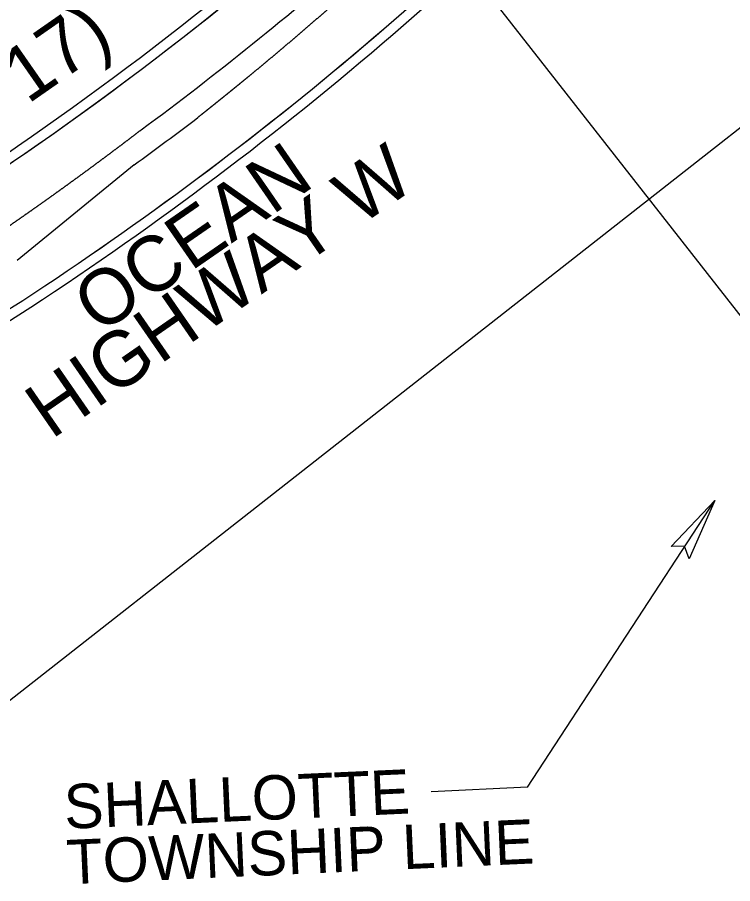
# Model space of a CAD drawing. Extents: x 2170913 to 2188101, y 74009 to 87693.
# Drawn here: x 2175946 to 2176656, y 76181 to 77040 of the extents above; entities that cross this region are included whole.
import ezdxf

# ---------------------------------------------------------------- set-up
doc = ezdxf.new("R2010")
doc.units = 0
for name, color, linetype in [('CTL Primary Horizontal and Vertical Cogo Elevation', 7, 'Continuous'), ('Exist Property Iron Pin CELL', 7, 'Continuous'), ('Exist Property Iron Pin Cogo Number', 7, 'Continuous'), ('Exist Right of Way Monument CELL', 7, 'Continuous'), ('Exist Utilities Water Fire Hydrant CELL', 7, 'Continuous')]:
    doc.layers.add(name, color=color, linetype=linetype)

msp = doc.modelspace()

# ---------------------------------------------------------------- linework, layer by layer
at = {"layer": 'CTL Primary Horizontal and Vertical Cogo Elevation'}
for q in [(2176638.43, 76560.83), (2176356.96, 76271.7)]:
    msp.add_line((2176452.51, 76276.24), q, dxfattribs=at)
at = {"layer": 'Exist Property Iron Pin Cogo Number'}
msp.add_lwpolyline([(2176595.29, 76515.13), (2176638.43, 76560.83), (2176613.16, 76502.86), (2176608.36, 76515.54)], close=True, dxfattribs=at)
at = {"layer": 'Exist Right of Way Monument CELL'}
for points in [[(2176389.16, 77095.58), (2177569.7, 78020.95), (2178217.46, 77194.57), (2177036.91, 76269.2)], [(2175120.11, 77054.97), (2176300.66, 77980.34), (2176948.42, 77153.96), (2175767.87, 76228.59)]]:
    msp.add_lwpolyline(points, close=True, dxfattribs=at)
at = {"layer": 'Exist Utilities Water Fire Hydrant CELL'}
msp.add_line((2176062.1, 76894.03), (2175946.01, 76799.04), dxfattribs=at)
msp.add_lwpolyline([(2176069.06, 76928.85), (2176069.05, 76928.86)], dxfattribs=at)
for radius, start, end in [(3256, 296.28229, 315.12361), (3266, 295.17779, 314.67638), (3266, 295.17779, 313.3768), (3396, 298.89848, 314.1103), (3386, 298.88447, 313.18402), (3386, 298.88447, 313.18162), (3314, 306.4358, 311.26548), (3338, 305.98475, 307.33893)]:
    msp.add_arc((2174100.8, 79595.05), radius, start, end, dxfattribs=at)
for points in [[(2176259.07, 77052.66), (2176258.85, 77052.47), (2176258.19, 77051.88), (2176257.53, 77051.3), (2176256.86, 77050.72), (2176256.2, 77050.14), (2176255.54, 77049.55), (2176254.87, 77048.97), (2176254.21, 77048.39), (2176253.55, 77047.81), (2176252.88, 77047.23), (2176252.22, 77046.65), (2176251.55, 77046.07), (2176250.89, 77045.49), (2176250.23, 77044.91), (2176249.56, 77044.32), (2176248.9, 77043.74), (2176248.23, 77043.16), (2176247.56, 77042.58), (2176246.9, 77042.01), (2176246.23, 77041.43), (2176245.57, 77040.85), (2176244.9, 77040.27), (2176244.24, 77039.69), (2176243.57, 77039.11), (2176242.9, 77038.53), (2176242.68, 77038.33)], [(2176242.68, 77038.33), (2176242.24, 77037.95), (2176241.57, 77037.37), (2176240.9, 77036.8), (2176240.24, 77036.22), (2176239.57, 77035.64), (2176238.9, 77035.06), (2176238.23, 77034.48), (2176237.57, 77033.91), (2176236.9, 77033.33), (2176236.23, 77032.75), (2176235.56, 77032.18), (2176234.89, 77031.6), (2176234.23, 77031.02), (2176233.56, 77030.45), (2176232.89, 77029.87), (2176232.22, 77029.3), (2176231.55, 77028.72), (2176230.88, 77028.14), (2176230.21, 77027.57), (2176229.54, 77026.99), (2176228.87, 77026.42), (2176228.2, 77025.84), (2176227.53, 77025.27), (2176226.86, 77024.69), (2176226.19, 77024.12)], [(2176226.19, 77024.12), (2176225.52, 77023.55), (2176224.85, 77022.97), (2176224.18, 77022.4), (2176223.51, 77021.82), (2176222.84, 77021.25), (2176222.17, 77020.68), (2176221.5, 77020.11), (2176220.83, 77019.53), (2176220.15, 77018.96), (2176219.48, 77018.39), (2176218.81, 77017.81), (2176218.14, 77017.24), (2176217.47, 77016.67), (2176216.79, 77016.1), (2176216.12, 77015.53), (2176215.45, 77014.96), (2176214.77, 77014.38), (2176214.1, 77013.81), (2176213.43, 77013.24), (2176212.76, 77012.67), (2176212.08, 77012.1), (2176211.41, 77011.53), (2176210.73, 77010.96), (2176210.06, 77010.39), (2176209.61, 77010.01)], [(2176209.61, 77010.01), (2176209.39, 77009.82), (2176208.71, 77009.25), (2176208.04, 77008.68), (2176207.36, 77008.11), (2176206.69, 77007.54), (2176206.01, 77006.97), (2176205.34, 77006.4), (2176204.66, 77005.83), (2176203.99, 77005.27), (2176203.31, 77004.7), (2176202.64, 77004.13), (2176201.96, 77003.56), (2176201.28, 77002.99), (2176200.61, 77002.43), (2176199.93, 77001.86), (2176199.26, 77001.29), (2176198.58, 77000.72), (2176197.9, 77000.16), (2176197.23, 76999.59), (2176196.55, 76999.02), (2176195.87, 76998.46), (2176195.19, 76997.89), (2176194.52, 76997.33), (2176193.84, 76996.76), (2176193.16, 76996.19), (2176192.93, 76996)], [(2176192.93, 76996), (2176192.48, 76995.63), (2176191.8, 76995.06), (2176191.13, 76994.5), (2176190.45, 76993.93), (2176189.77, 76993.37), (2176189.09, 76992.8), (2176188.41, 76992.24), (2176187.73, 76991.67), (2176187.05, 76991.11), (2176186.37, 76990.55), (2176185.69, 76989.98), (2176185.01, 76989.42), (2176184.34, 76988.86), (2176183.66, 76988.29), (2176182.97, 76987.73), (2176182.29, 76987.17), (2176181.61, 76986.6), (2176180.93, 76986.04), (2176180.25, 76985.48), (2176179.57, 76984.92), (2176178.89, 76984.36), (2176178.21, 76983.79), (2176177.53, 76983.23), (2176176.85, 76982.67), (2176176.16, 76982.11)], [(2176052.36, 76916.15), (2176052.83, 76916.5), (2176053.53, 76917.03), (2176054.23, 76917.56), (2176054.93, 76918.09), (2176055.63, 76918.62), (2176056.33, 76919.15), (2176057.03, 76919.68), (2176057.72, 76920.21), (2176058.42, 76920.74), (2176059.12, 76921.27), (2176059.82, 76921.8), (2176060.52, 76922.33), (2176061.21, 76922.87), (2176061.91, 76923.4), (2176062.61, 76923.93), (2176063.31, 76924.46), (2176064.01, 76924.99), (2176064.7, 76925.52), (2176065.4, 76926.06), (2176066.1, 76926.59), (2176066.79, 76927.12), (2176067.49, 76927.65), (2176068.19, 76928.19), (2176069.06, 76928.85)], [(2176035.06, 76903.16), (2176035.3, 76903.34), (2176036, 76903.86), (2176036.7, 76904.39), (2176037.41, 76904.91), (2176038.11, 76905.44), (2176038.81, 76905.96), (2176039.51, 76906.49), (2176040.21, 76907.01), (2176040.92, 76907.54), (2176041.62, 76908.07), (2176042.32, 76908.59), (2176043.02, 76909.12), (2176043.72, 76909.64), (2176044.43, 76910.17), (2176045.13, 76910.7), (2176045.83, 76911.22), (2176046.53, 76911.75), (2176047.23, 76912.28), (2176047.93, 76912.81), (2176048.63, 76913.33), (2176049.33, 76913.86), (2176050.03, 76914.39), (2176050.73, 76914.92), (2176051.43, 76915.45), (2176052.13, 76915.98), (2176052.36, 76916.15)], [(2176017.67, 76890.29), (2176018.38, 76890.81), (2176019.09, 76891.33), (2176019.79, 76891.85), (2176020.5, 76892.37), (2176021.21, 76892.89), (2176021.91, 76893.41), (2176022.62, 76893.93), (2176023.32, 76894.45), (2176024.03, 76894.97), (2176024.73, 76895.49), (2176025.44, 76896.02), (2176026.14, 76896.54), (2176026.85, 76897.06), (2176027.55, 76897.58), (2176028.26, 76898.1), (2176028.96, 76898.63), (2176029.67, 76899.15), (2176030.37, 76899.67), (2176031.07, 76900.2), (2176031.78, 76900.72), (2176032.48, 76901.24), (2176033.19, 76901.77), (2176033.89, 76902.29), (2176034.59, 76902.81), (2176035.06, 76903.16)], [(2176000.2, 76877.52), (2176000.67, 76877.87), (2176001.38, 76878.38), (2176002.09, 76878.9), (2176002.8, 76879.41), (2176003.51, 76879.93), (2176004.22, 76880.45), (2176004.93, 76880.96), (2176005.64, 76881.48), (2176006.35, 76881.99), (2176007.06, 76882.51), (2176007.77, 76883.03), (2176008.48, 76883.55), (2176009.18, 76884.06), (2176009.89, 76884.58), (2176010.6, 76885.1), (2176011.31, 76885.62), (2176012.02, 76886.14), (2176012.72, 76886.65), (2176013.43, 76887.17), (2176014.14, 76887.69), (2176014.85, 76888.21), (2176015.55, 76888.73), (2176016.26, 76889.25), (2176016.97, 76889.77), (2176017.67, 76890.29)], [(2175982.64, 76864.87), (2175982.88, 76865.04), (2175983.59, 76865.55), (2175984.31, 76866.06), (2175985.02, 76866.57), (2175985.73, 76867.09), (2175986.44, 76867.6), (2175987.16, 76868.11), (2175987.87, 76868.62), (2175988.58, 76869.13), (2175989.29, 76869.65), (2175990.01, 76870.16), (2175990.72, 76870.67), (2175991.43, 76871.18), (2175992.14, 76871.7), (2175992.85, 76872.21), (2175993.57, 76872.72), (2175994.28, 76873.24), (2175994.99, 76873.75), (2175995.7, 76874.26), (2175996.41, 76874.78), (2175997.12, 76875.29), (2175997.83, 76875.81), (2175998.54, 76876.32), (2175999.25, 76876.84), (2175999.96, 76877.35), (2176000.2, 76877.52)], [(2175965, 76852.33), (2175965.71, 76852.84), (2175966.43, 76853.35), (2175967.15, 76853.85), (2175967.86, 76854.36), (2175968.58, 76854.87), (2175969.3, 76855.37), (2175970.01, 76855.88), (2175970.73, 76856.39), (2175971.44, 76856.89), (2175972.16, 76857.4), (2175972.88, 76857.91), (2175973.59, 76858.42), (2175974.31, 76858.93), (2175975.02, 76859.44), (2175975.74, 76859.94), (2175976.45, 76860.45), (2175977.17, 76860.96), (2175977.88, 76861.47), (2175978.59, 76861.98), (2175979.31, 76862.49), (2175980.02, 76863), (2175980.74, 76863.51), (2175981.45, 76864.02), (2175982.16, 76864.53), (2175982.64, 76864.87)], [(2175947.27, 76839.91), (2175947.75, 76840.24), (2175948.47, 76840.75), (2175949.19, 76841.25), (2175949.91, 76841.75), (2175950.63, 76842.25), (2175951.35, 76842.75), (2175952.07, 76843.26), (2175952.79, 76843.76), (2175953.51, 76844.26), (2175954.23, 76844.76), (2175954.95, 76845.27), (2175955.67, 76845.77), (2175956.38, 76846.28), (2175957.1, 76846.78), (2175957.82, 76847.28), (2175958.54, 76847.79), (2175959.26, 76848.29), (2175959.98, 76848.8), (2175960.69, 76849.3), (2175961.41, 76849.81), (2175962.13, 76850.31), (2175962.85, 76850.82), (2175963.56, 76851.32), (2175964.28, 76851.83), (2175965, 76852.33)], [(2175929.46, 76827.6), (2175929.7, 76827.77), (2175930.43, 76828.26), (2175931.15, 76828.76), (2175931.87, 76829.26), (2175932.6, 76829.75), (2175933.32, 76830.25), (2175934.04, 76830.75), (2175934.76, 76831.25), (2175935.49, 76831.75), (2175936.21, 76832.24), (2175936.93, 76832.74), (2175937.65, 76833.24), (2175938.38, 76833.74), (2175939.1, 76834.24), (2175939.82, 76834.74), (2175940.54, 76835.24), (2175941.26, 76835.74), (2175941.98, 76836.24), (2175942.71, 76836.74), (2175943.43, 76837.24), (2175944.15, 76837.74), (2175944.87, 76838.24), (2175945.59, 76838.74), (2175946.31, 76839.24), (2175947.03, 76839.74), (2175947.27, 76839.91)]]:
    msp.add_spline(points, degree=3, dxfattribs=at)
for points in [[(2176176.16, 76982.11), (2176175.94, 76981.92), (2176175.71, 76981.74), (2176175.48, 76981.55), (2176175.26, 76981.36), (2176175.03, 76981.17), (2176174.8, 76980.99), (2176174.57, 76980.8), (2176174.35, 76980.61), (2176174.12, 76980.43), (2176173.89, 76980.24), (2176173.66, 76980.05), (2176173.44, 76979.87), (2176173.21, 76979.68), (2176172.98, 76979.49), (2176172.76, 76979.31), (2176172.53, 76979.12), (2176172.3, 76978.93), (2176172.07, 76978.75), (2176171.85, 76978.56), (2176171.62, 76978.37), (2176171.39, 76978.19), (2176171.16, 76978), (2176170.93, 76977.81), (2176170.71, 76977.63), (2176170.48, 76977.44), (2176170.25, 76977.25), (2176170.02, 76977.07), (2176169.8, 76976.88), (2176169.57, 76976.69), (2176169.34, 76976.51), (2176169.11, 76976.32), (2176168.89, 76976.13), (2176168.66, 76975.95), (2176168.43, 76975.76), (2176168.2, 76975.57), (2176167.97, 76975.39), (2176167.75, 76975.2), (2176167.52, 76975.02), (2176167.29, 76974.83), (2176167.06, 76974.64), (2176166.83, 76974.46), (2176166.61, 76974.27), (2176166.38, 76974.08), (2176166.15, 76973.9), (2176165.92, 76973.71), (2176165.69, 76973.53), (2176165.47, 76973.34), (2176165.24, 76973.15), (2176165.01, 76972.97), (2176164.78, 76972.78), (2176164.55, 76972.59), (2176164.33, 76972.41), (2176164.1, 76972.22), (2176163.87, 76972.04), (2176163.64, 76971.85), (2176163.41, 76971.66), (2176163.19, 76971.48), (2176162.96, 76971.29), (2176162.73, 76971.11), (2176162.5, 76970.92), (2176162.27, 76970.74), (2176162.04, 76970.55), (2176161.82, 76970.36), (2176161.59, 76970.18), (2176161.36, 76969.99), (2176161.13, 76969.81), (2176160.9, 76969.62), (2176160.67, 76969.43), (2176160.45, 76969.25), (2176160.22, 76969.06), (2176159.99, 76968.88), (2176159.76, 76968.69), (2176159.62, 76968.58), (2176159.47, 76968.46), (2176159.33, 76968.34)], [(2176159.33, 76968.34), (2176159.25, 76968.27), (2176159.16, 76968.2), (2176159.08, 76968.14), (2176158.85, 76967.95), (2176158.62, 76967.76), (2176158.39, 76967.58), (2176158.16, 76967.39), (2176157.93, 76967.21), (2176157.7, 76967.02), (2176157.48, 76966.84), (2176157.25, 76966.65), (2176157.02, 76966.47), (2176156.79, 76966.28), (2176156.56, 76966.1), (2176156.33, 76965.91), (2176156.1, 76965.72), (2176155.88, 76965.54), (2176155.65, 76965.35), (2176155.42, 76965.17), (2176155.19, 76964.98), (2176154.96, 76964.8), (2176154.73, 76964.61), (2176154.5, 76964.43), (2176154.27, 76964.24), (2176154.04, 76964.06), (2176153.82, 76963.87), (2176153.59, 76963.69), (2176153.36, 76963.5), (2176153.13, 76963.32), (2176152.9, 76963.13), (2176152.67, 76962.95), (2176152.44, 76962.76), (2176152.21, 76962.58), (2176151.98, 76962.39), (2176151.76, 76962.21), (2176151.53, 76962.02), (2176151.3, 76961.84), (2176151.07, 76961.65), (2176150.84, 76961.47), (2176150.61, 76961.28), (2176150.38, 76961.1), (2176150.15, 76960.91), (2176149.92, 76960.73), (2176149.69, 76960.54), (2176149.46, 76960.36), (2176149.23, 76960.17), (2176149.01, 76959.99), (2176148.78, 76959.8), (2176148.55, 76959.62), (2176148.32, 76959.44), (2176148.09, 76959.25), (2176147.86, 76959.07), (2176147.63, 76958.88), (2176147.4, 76958.7), (2176147.17, 76958.51), (2176146.94, 76958.33), (2176146.71, 76958.14), (2176146.48, 76957.96), (2176146.25, 76957.77), (2176146.02, 76957.59), (2176145.79, 76957.41), (2176145.57, 76957.22), (2176145.34, 76957.04), (2176145.11, 76956.85), (2176144.88, 76956.67), (2176144.65, 76956.48), (2176144.42, 76956.3), (2176144.19, 76956.12), (2176143.96, 76955.93), (2176143.73, 76955.75), (2176143.5, 76955.56), (2176143.27, 76955.38), (2176143.04, 76955.19), (2176142.81, 76955.01), (2176142.58, 76954.83), (2176142.52, 76954.78), (2176142.46, 76954.73), (2176142.4, 76954.68)], [(2176142.4, 76954.68), (2176142.23, 76954.55), (2176142.06, 76954.41), (2176141.89, 76954.27), (2176141.66, 76954.09), (2176141.43, 76953.91), (2176141.2, 76953.72), (2176140.97, 76953.54), (2176140.74, 76953.35), (2176140.51, 76953.17), (2176140.28, 76952.99), (2176140.05, 76952.8), (2176139.82, 76952.62), (2176139.59, 76952.43), (2176139.36, 76952.25), (2176139.13, 76952.07), (2176138.9, 76951.88), (2176138.67, 76951.7), (2176138.44, 76951.51), (2176138.21, 76951.33), (2176137.98, 76951.15), (2176137.75, 76950.96), (2176137.52, 76950.78), (2176137.29, 76950.6), (2176137.06, 76950.41), (2176136.83, 76950.23), (2176136.6, 76950.05), (2176136.37, 76949.86), (2176136.14, 76949.68), (2176135.91, 76949.49), (2176135.68, 76949.31), (2176135.45, 76949.13), (2176135.22, 76948.94), (2176134.99, 76948.76), (2176134.76, 76948.58), (2176134.53, 76948.39), (2176134.3, 76948.21), (2176134.07, 76948.03), (2176133.84, 76947.84), (2176133.61, 76947.66), (2176133.38, 76947.48), (2176133.15, 76947.29), (2176132.92, 76947.11), (2176132.69, 76946.93), (2176132.46, 76946.74), (2176132.23, 76946.56), (2176132, 76946.38), (2176131.77, 76946.19), (2176131.54, 76946.01), (2176131.31, 76945.83), (2176131.08, 76945.64), (2176130.84, 76945.46), (2176130.61, 76945.28), (2176130.38, 76945.09), (2176130.15, 76944.91), (2176129.92, 76944.73), (2176129.69, 76944.55), (2176129.46, 76944.36), (2176129.23, 76944.18), (2176129, 76944), (2176128.77, 76943.81), (2176128.54, 76943.63), (2176128.31, 76943.45), (2176128.08, 76943.26), (2176127.85, 76943.08), (2176127.62, 76942.9), (2176127.39, 76942.72), (2176127.15, 76942.53), (2176126.92, 76942.35), (2176126.69, 76942.17), (2176126.46, 76941.99), (2176126.23, 76941.8), (2176126, 76941.62), (2176125.8, 76941.46), (2176125.59, 76941.3), (2176125.39, 76941.14)]]:
    msp.add_open_spline(points, degree=3, dxfattribs=at)

# ---------------------------------------------------------------- texts
at = {"layer": 'Exist Property Iron Pin CELL'}
for s, height, rotation, p in [('-L- (US 17)', 55.0465, 34.86558, (2175744.94, 76806.49)), ('HIGHWAY W', 55.047, 34.6672, (2175979.86, 76621.01)), ('OCEAN ', 55.047, 34.6672, (2176027.37, 76725.04)), ('SHALLOTTE', 44.037, 2.56951, (2175993.34, 76234.87)), ('TOWNSHIP LINE', 44.0372, 2.56951, (2175995.81, 76179.88))]:
    msp.add_text(s, height=height, rotation=rotation, dxfattribs=at).set_placement(p)

doc.saveas('drawing.dxf')
